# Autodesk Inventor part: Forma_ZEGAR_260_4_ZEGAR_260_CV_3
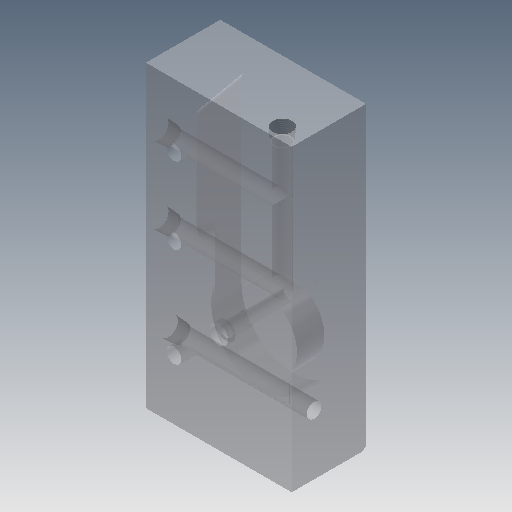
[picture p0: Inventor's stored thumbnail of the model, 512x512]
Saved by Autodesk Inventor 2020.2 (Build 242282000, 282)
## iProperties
Created: 2015-01
Part Number: Forma_ZEGAR_260_4_ZEGAR_260_CV_3
Material: Ogólny
Document SubType Name: Modeling
Designer: F.Stasiak
Density: 1 g/cm^3
Appearance: Domyślna
Catalog Web Link: www.expertbooks.pl
Manager: www.cadconsulting.pl
Company: Fabian Stasiak CAD Consulting
Author: F.Stasiak
Subject: Zbiór ćwiczeń. Autodesk Inventor 2020. Kurs Professional
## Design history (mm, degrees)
node "Forma_ZEGAR_260_4_ZEGAR_260_CV_Base"
feature "Rzeźbienie3"
feature "Rzeźbienie4"
feature "Gwint1" dims "d0" = 0, "d1" = 0
feature "Rzeźbienie13"
feature "Rzeźbienie14"
feature "Gwint6" dims "d10" = 0, "d11" = 0
feature "Rzeźbienie15"
feature "Gwint7" dims "d12" = 0, "d13" = 0
feature "Rzeźbienie16"
feature "Gwint8" dims "d14" = 0, "d15" = 0
feature "Rzeźbienie17"
feature "Rzeźbienie18"
feature "Bryła1::Forma_ZEGAR_260_4_ZEGAR_260_CV_Base"
tag "Bryła wyprowadzona1"
node "Bryła1"
feature "Forma_ZEGAR_260_4_ZEGAR_260_CV_Base_Bodies"
feature "Powierzchnia3"
body "Srf3"
feature "Powierzchnia4"
body "Srf4"
feature "Powierzchnia13"
body "Srf13"
feature "Powierzchnia14"
body "Srf14"
feature "Powierzchnia15"
body "Srf15"
feature "Powierzchnia16"
body "Srf16"
feature "Powierzchnia17"
body "Srf17"
feature "Powierzchnia18"
body "Srf18"
